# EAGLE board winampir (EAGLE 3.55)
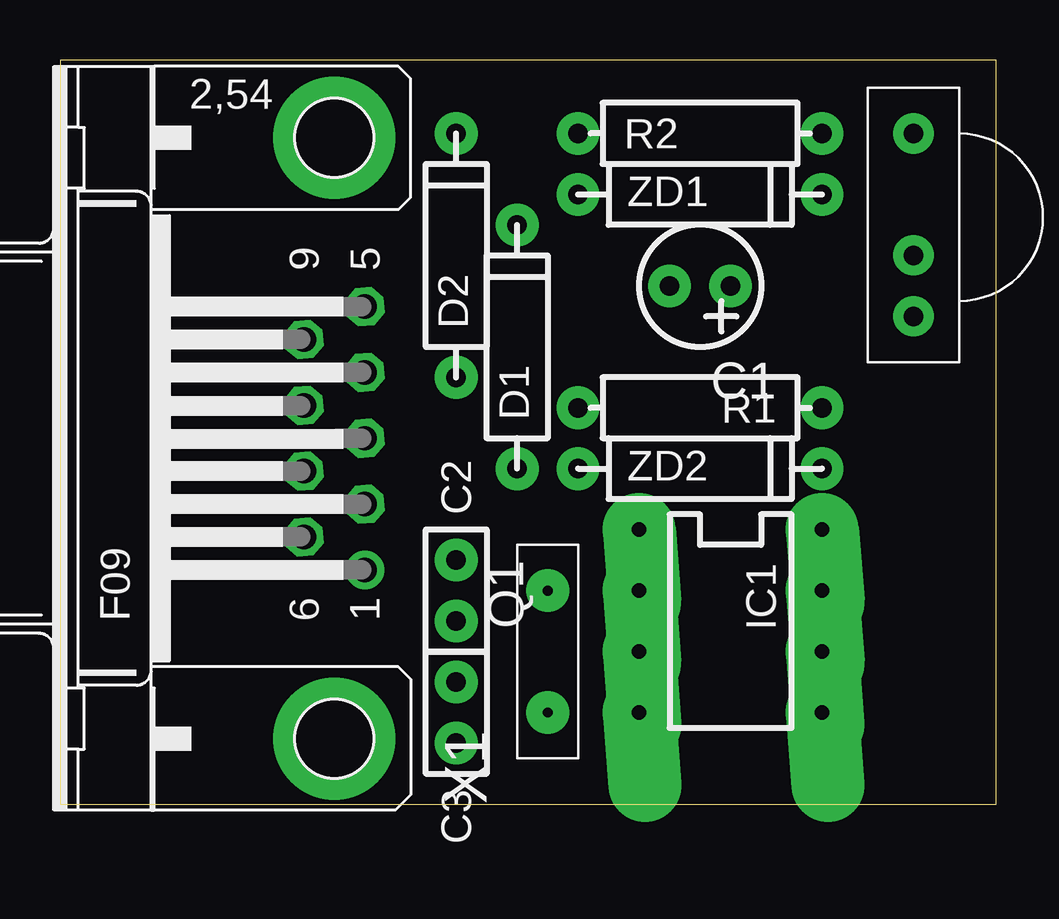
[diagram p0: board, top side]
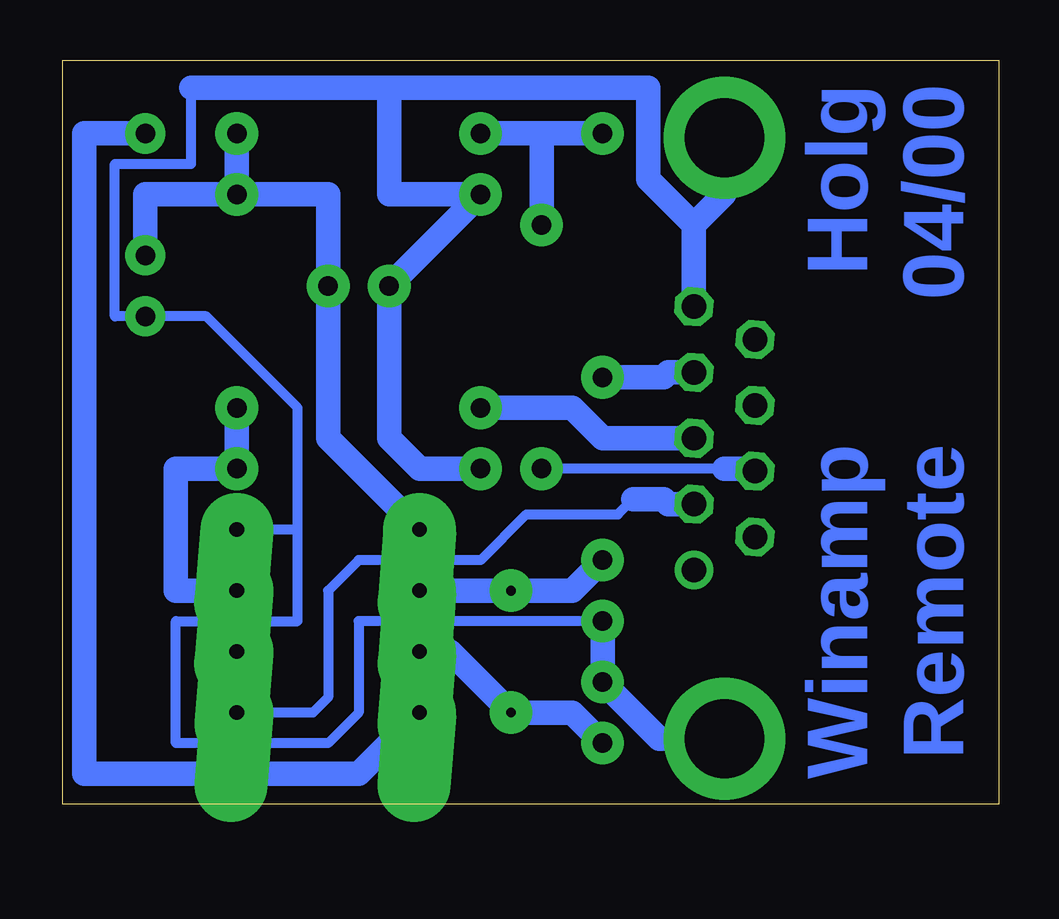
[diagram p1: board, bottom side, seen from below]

Size 39 x 31 mm. Coordinates in mm from the lower left corner, seen from the top.
Outline: 0,0 39,0 39,31 0,31 0,0
Copper layers used: Bottom

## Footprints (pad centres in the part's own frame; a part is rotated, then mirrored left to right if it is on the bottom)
KO01 = drill 0.813 pad 1.778 round:  0,0;  2.54,0
RM2,5 = drill 0.813 pad 1.778 round:  0,0;  2.54,0
O04 = drill 0.813 pad 1.778 round:  0,0;  10.16,0
L-8B = drill 0.61 pad 3.048 offset:  0,0;  2.54,0;  5.08,0;  7.62,0;  7.62,7.62;  5.08,7.62;  2.54,7.62;  0,7.62
OP1736 = drill 0.813 pad 1.676 round: A 7.62,0;  0,0;  2.54,0
ARZ_ST = drill 0.406 pad 1.778 round:  0,0;  5.08,0
S04 = drill 0.813 pad 1.778 round:  0,0;  10.16,0
9HP = drill 1.016 pad 1.6 round:  -5.486,-1.27 | drill 1.016 pad 1.6 octagon:  -2.743,-1.27;  0,-1.27;  2.743,-1.27;  5.486,-1.27;  -4.115,1.27;  -1.372,1.27;  1.372,1.27;  4.115,1.27 | drill 3.302 pad 5.08 round:  -12.522,0;  12.522,0

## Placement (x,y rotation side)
C1  4u7  [KO01]  27.94,21.59 180 top
C2  15-22p  [RM2,5]  16.51,7.62 90 top
C3  15-22p  [RM2,5]  16.51,5.08 270 top
D1  1N4148  [O04]  19.05,13.97 90 top
D2  1N4148  [O04]  16.51,17.78 90 top
IC1  12C509P  [L-8B]  24.13,11.43 270 top
IC2  TSOP1736  [OP1736]  35.56,20.32 90 top
Q1  4MHz  [ARZ_ST]  20.32,8.89 270 top
R1  33k  [S04]  31.75,16.51 180 top
R2  1k  [S04]  21.59,27.94 0 top
X1  F09HP  [9HP]  11.43,15.24 90 top
ZD1  5V1  [O04]  21.59,25.4 0 top
ZD2  5V1  [O04]  21.59,13.97 0 top

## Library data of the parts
C1-C3 D1 D2 R1 R2 ZD1 ZD2 = holgeins
IC1 Q1 = holg_plt
IC2 = ic_holg
X1 = subd-a

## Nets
GND: C1. C2. C3. IC1. IC2. X1. ZD1. ZD2.
N$1: IC1. R1. ZD2.
N$2: C1. IC1. IC2. R2. ZD1.
N$3: D2. X1.
N$4: D1. X1.
N$6: D1. D2. R2.
N$7: IC1. IC2.A
N$8: C3. IC1. Q1.
N$9: C2. IC1. Q1.
RXD: IC1. X1.
TXD: R1. X1.

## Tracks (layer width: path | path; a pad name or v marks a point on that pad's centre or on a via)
GND
  Bottom 0.406: 33.66,29.84 33.66,26.67 36.83,26.67 36.83,20.32 35.56,20.32 33.02,20.32 29.21,16.51 29.21,11.43 | 29.21,11.43 IC1. | 16.51,7.62 26.67,7.62 26.67,3.81 27.94,2.54 34.29,2.54 34.29,7.62 29.21,7.62 29.21,11.43
  Bottom 1.016: 16.51,7.62 16.51,5.08 14.15,2.72 11.43,2.72 | 21.59,13.97 24.13,13.97 25.4,15.24 C1. 21.59,25.4 25.4,25.4 25.4,29.84 | 33.66,29.84 25.4,29.84 | 12.7,24.13 12.7,20.73 | 12.7,24.13 14.61,26.04 14.61,29.84 25.4,29.84 | X1. 11.43,25.4 12.7,24.13
N$1
  Bottom 1.016: 31.75,16.51 ZD2. 34.29,13.97 34.29,8.89 31.75,8.89
N$2
  Bottom 1.016: ZD1. R2. | ZD1. 35.56,25.4 IC2. | ZD1. 27.94,25.4 27.94,21.59 27.94,15.24 24.13,11.43
N$3
  Bottom 1.016: 12.7,17.98 13.77,17.98 13.97,17.78 16.51,17.78
N$4
  Bottom 0.406: 11.43,13.97 19.05,13.97
  Bottom 1.016: 10.16,13.87 10.26,13.97 11.43,13.97
N$6
  Bottom 1.016: 19.05,27.94 21.59,27.94 | 19.05,27.94 D2. | D1. 19.05,27.94
N$7
  Bottom 1.016: 24.13,3.81 26.67,1.27 38.1,1.27 38.1,27.94 IC2.A
N$8
  Bottom 1.016: C3. 17.78,3.81 Q1. 22.86,6.35 24.13,6.35
N$9
  Bottom 1.016: 24.13,8.89 20.32,8.89 17.78,8.89 C2.
RXD
  Bottom 0.406: 31.75,3.81 28.57,3.81 27.94,4.45 27.94,8.89 26.67,10.16 21.59,10.16 19.68,12.06 15.88,12.06 15.24,12.7
  Bottom 1.016: 12.7,12.5 13.77,12.5 13.97,12.7 15.24,12.7
TXD
  Bottom 1.016: 12.7,15.24 16.51,15.24 17.78,16.51 R1.

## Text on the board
Bottom: 04/00 | Holg | Remote | Winamp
